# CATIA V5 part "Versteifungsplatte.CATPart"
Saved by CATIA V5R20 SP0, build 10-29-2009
Part number: Versteifungsplatte
Bounding box of the stored display mesh (mm): x 0 to 6, y -70 to 70, z -135 to 135
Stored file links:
  C:\Users\Andi\Desktop\Offene Projekte\Plasmacutter\Z-Achse\Versteifungsplatte.CATPart
  C:\Program Files\Dassault Systemes\B20\win_b64\reffiles\standard\MetricThickPitch.txt
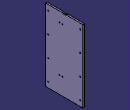
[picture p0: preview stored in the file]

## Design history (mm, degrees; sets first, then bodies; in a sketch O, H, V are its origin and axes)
Body1 (main body)
  Sketch1 on yz-plane, origin (0, 0, 0), H (0, 1, 0), V (0, 0, 1)
    line L1 (70, 135) -> (70, -135)
    line L2 (70, -135) -> (-70, -135)
    line L3 (-70, -135) -> (-70, 135)
    line L4 (-70, 135) -> (-7.4721, 135)
    line L5 (3, 133) -> (-3, 133)
    arc A1 centre (3, 139) radius 6 from (3, 133) to (7.4721, 135) ccw
    point P7 (3, 139)
    point P8 (7.4721, 135)
    arc A2 centre (-3, 139) radius 6 from (-7.4721, 135) to (-3, 133) ccw
    point P9 (-3, 139)
    line L6 (7.4721, 135) -> (70, 135)
    distance L2 L4 = 270
    distance L1 L3 = 140
    distance P9 P7 = 6
    distance L5 L6 = 2
    radius A2 = 6
    vertical: L1 V, L3 V
    horizontal: L2 H, L4 H, L5 H, L6 H
    equidistance: L1 L3 O, L2 L4 O
    tangency: A1 L5, A2 L5
    coincidence: P8 L4, L4 L6
    symmetry: A2 A1 V
  Pad1: profile Sketch1, direction (1, 0, 0), length 6
  Sketch2 on end face of Pad1, origin (6, -0.6209, 101.3963), H (0, 1, 0), V (0, 0, 1)
    point P1 (-6.3791, -3.3963)
    reference intersected line E1 through (0.6209, 0) direction (0, 1) from zx-plane
    reference intersected line E2 through (0, -101.3963) direction (-1, 0) from xy-plane
    distance E1 P1 = 7
    distance E2 P1 = 98
  Hole1: placed by Sketch2, at (6, -7, 98) direction (-1, 0, 0), diameter 3.242, through (limit type 6), threaded "M4", thread diameter 4, thread depth 6, pitch 0.7
  RectPattern1: of Hole1, direction 1 instances 2, spacing 11, along end face of Pad1 reversed, direction 2 instances 2, spacing 170, along end face of Pad1 reversed
  Sketch3 on end face of Pad1, origin (6, -61.6535, 124.5294), H (0, 1, 0), V (0, 0, 1)
    point P1 (1.6535, -9.5294)
    reference intersected line E1 through (61.6535, 0) direction (0, 1) from zx-plane
    reference projected line E2 (131.6535, 10.4706) -> (-8.3465, 10.4706) from edge [face of Pad1 from Sketch1.L4 | end face of Pad1]
    distance P1 E1 = 60
    distance E2 P1 = 20
  Hole2: placed by Sketch3, at (6, -60, 115) direction (-1, 0, 0), diameter 4.5, through (limit type 6)
  RectPattern2: of Hole2, direction 1 instances 2, spacing 120, along end face of Pad1, direction 2 instances 4, spacing 76.6667, along end face of Pad1 reversed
